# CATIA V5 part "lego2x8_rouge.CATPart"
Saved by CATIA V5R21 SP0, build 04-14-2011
Part number: lego2x8_rouge
Definition: Brique LEGO® 2x8, couleur Rouge
Description: Brique LEGO® 2x8, couleur Rouge
Property "SUPPLIER": "LEGO®"
Property "SUPPLIER": "LEGO®"
Property "DESIGN": "Brique LEGO® 2x8, couleur Rouge"
Property "DESIGN": "Brique LEGO® 2x8, couleur Rouge"
Property "TraceParts.PartNumber": "10-20122010-070686"
Property "TRACEPARTS": "TRACEPARTS"
Property "TraceParts.PartTitle": "Brique LEGO® 2x8"
Property "TraceParts.InstanceId": "10-20122010-07068610UFQ9W313DGN2O2A8ITDW7CR"
Property "TraceParts.PartVersion": "1.0.7"
Property "TraceParts.PartLanguage": "fr"
Bounding box of the stored display mesh (mm): x -4 to 60, y 0 to 11.2, z -4 to 12
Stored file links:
  C:\Users\2027.DESARCY-LEMIE30\Desktop\Legos\traité\lego2x8_rouge.CATPart
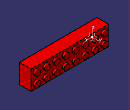
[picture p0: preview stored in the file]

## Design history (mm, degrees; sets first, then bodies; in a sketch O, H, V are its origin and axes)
AxisSystem1: origin (0, 0, 0), X (1, 0, 0), Y (0, 1, 0), Z (0, 0, 1)
Body1 "lego2x8_rouge" (main body)
  Solid1: solid without history
  Sketch1 on face of Solid1, origin (0, 0, 0), H (1, 0, 0), V (0, 0, 1)
    line L1 (-3, 11) -> (59, 11)
    line L2 (59, 11) -> (59, -3)
    line L3 (59, -3) -> (-3, -3)
    line L4 (-3, -3) -> (-3, 11)
    reference projected line E1 (-4, 12) -> (60, 12) from edge [face of Solid1 | face of Solid1]
    reference projected line E2 (60, -4) -> (60, 12) from edge [face of Solid1 | face of Solid1]
    reference projected line E3 (-4, -4) -> (60, -4) from edge [face of Solid1 | face of Solid1]
    reference projected line E4 (-4, -4) -> (-4, 12) from edge [face of Solid1 | face of Solid1]
    circle A1 centre (52, 4) radius 3
    circle A2 centre (36, 4) radius 3
    point P7 (44, 4)
    circle A3 centre (44, 4) radius 3
    circle A4 centre (28, 4) radius 3
    circle A5 centre (20, 4) radius 3
    circle A6 centre (12, 4) radius 3
    circle A7 centre (4, 4) radius 3
    reference projected circle E5 centre (52, 4) radius 2.4 from edge [face of Solid1 | face of Solid1]
    reference projected circle E6 centre (44, 4) radius 2.4 from edge [face of Solid1 | face of Solid1]
    reference projected circle E7 centre (36, 4) radius 2.4 from edge [face of Solid1 | face of Solid1]
    reference projected circle E8 centre (28, 4) radius 2.4 from edge [face of Solid1 | face of Solid1]
    reference projected circle E9 centre (20, 4) radius 2.4 from edge [face of Solid1 | face of Solid1]
    reference projected circle E10 centre (12, 4) radius 2.4 from edge [face of Solid1 | face of Solid1]
    reference projected circle E11 centre (4, 4) radius 2.4 from edge [face of Solid1 | face of Solid1]
    circle A8 centre (52, 4) radius 2.4
    reference projected circle E12 centre (52, 4) radius 2.4 from edge [face of Solid1 | face of Solid1]
    circle A9 centre (44, 4) radius 2.4
    circle A10 centre (36, 4) radius 2.4
    circle A11 centre (28, 4) radius 2.4
    circle A12 centre (20, 4) radius 2.4
    circle A13 centre (12, 4) radius 2.4
    circle A14 centre (4, 4) radius 2.4
    reference projected circle E13 centre (44, 4) radius 2.4 from edge [face of Solid1 | face of Solid1]
    reference projected circle E14 centre (36, 4) radius 2.4 from edge [face of Solid1 | face of Solid1]
    reference projected circle E15 centre (28, 4) radius 2.4 from edge [face of Solid1 | face of Solid1]
    reference projected circle E16 centre (20, 4) radius 2.4 from edge [face of Solid1 | face of Solid1]
    reference projected circle E17 centre (12, 4) radius 2.4 from edge [face of Solid1 | face of Solid1]
    reference projected circle E18 centre (4, 4) radius 2.4 from edge [face of Solid1 | face of Solid1]
    distance L1 E1 = 1
    distance L2 E2 = 1
    distance L3 E3 = 1
    distance E4 L4 = 1
    radius A1 = 3
    radius A3 = 3
    radius A2 = 3
    radius A4 = 3
    radius A5 = 3
    radius A6 = 3
    radius A7 = 3
    horizontal: L1 H, L3 H
    vertical: L2 V, L4 V
    concentricity: A1 E5, P7 E6, A2 E7, E8 A4, E9 A5, E10 A6, E11 A7
    coincidence: A8 E12, A9 E13, A10 E14, A11 E15, A12 E16, A13 E17, A14 E18
  Pocket1: profile Sketch1, direction (0, 1, 0), length 9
